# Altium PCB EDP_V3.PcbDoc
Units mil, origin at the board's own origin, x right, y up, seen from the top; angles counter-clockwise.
Board outline 1496.06 x 2204.77 mil, 2 copper layers (Top Layer, Bottom Layer); 19 components, 14 nets, 61 pads, 4 vias.
Unrouted connection lines stored in the file: 1.
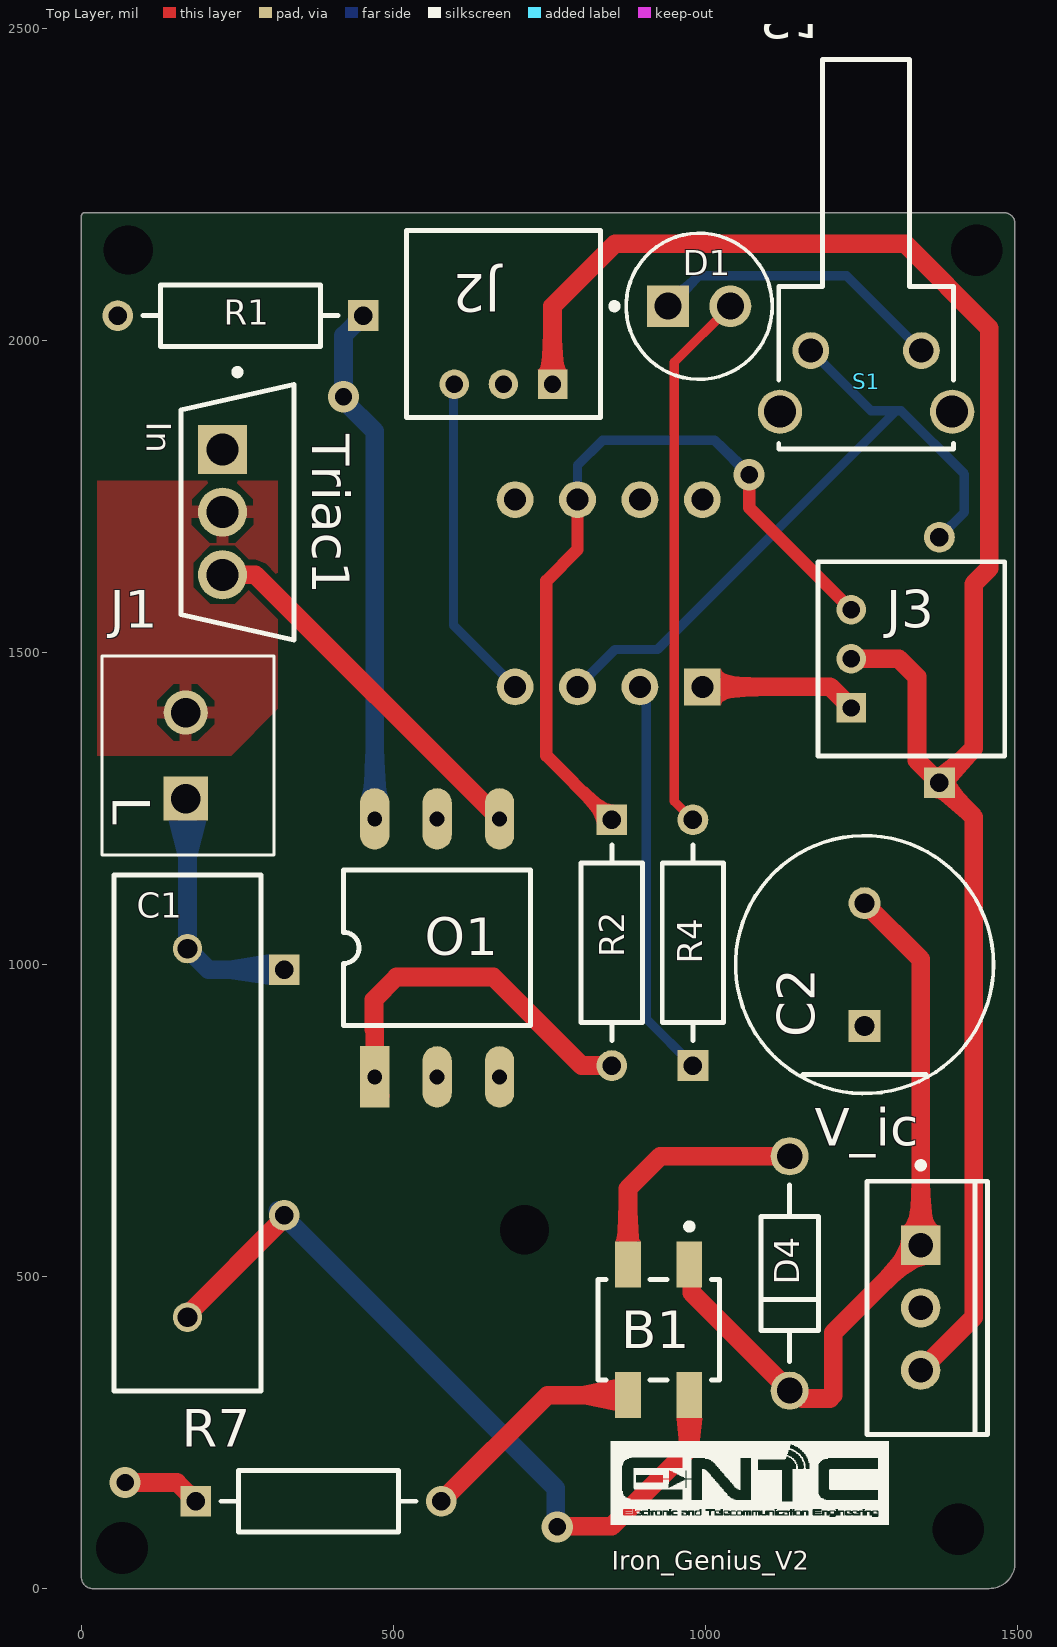
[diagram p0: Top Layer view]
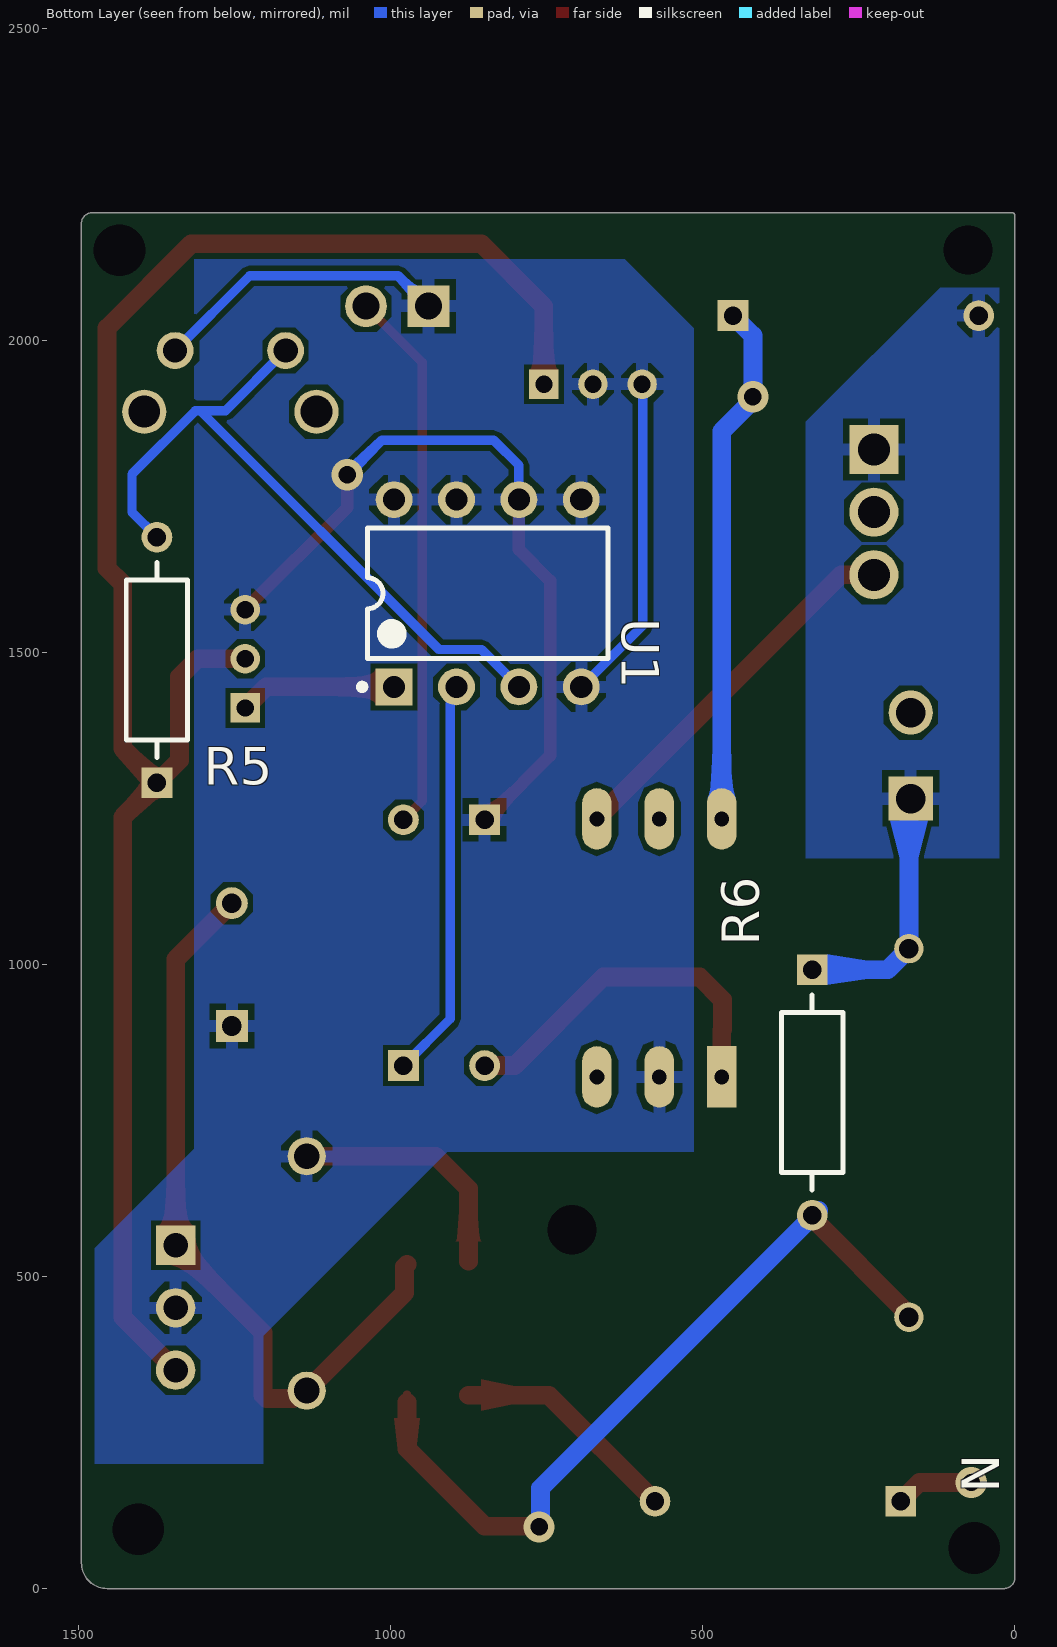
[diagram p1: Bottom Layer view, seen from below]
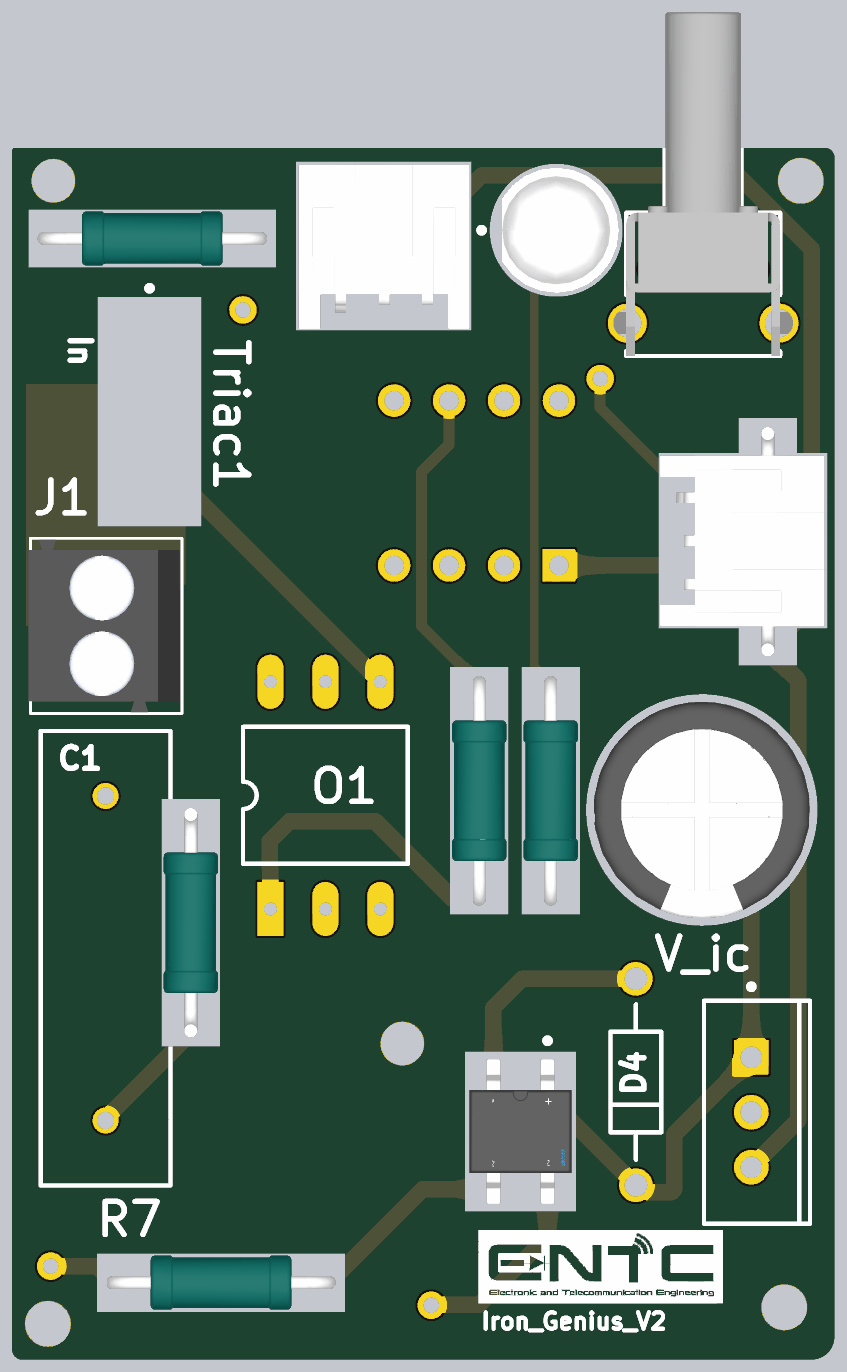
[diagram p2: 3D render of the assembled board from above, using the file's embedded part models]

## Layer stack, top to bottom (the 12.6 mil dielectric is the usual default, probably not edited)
Top Solder: solder mask 1, SM-001, Dk 4
Top Layer: signal copper 1.4
Dielectric 1: dielectric 12.6, FR-4, Dk 4.8
Bottom Layer: signal copper 1.4
Bottom Solder: solder mask 1, SM-001, Dk 4

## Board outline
0,18 0,2200 cw(c4.78,2200) 5.08,2204.77 cw(c5.23,2200.5) 5.9,2204.72 1479.28,2204.72 cw(c1479.28,2187.94) 1496.06,2187.94 1496.06,41.06 cw(c1455,41.06) 1455,0 18,0 cw(c18,18)

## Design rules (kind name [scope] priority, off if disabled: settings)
BoardOutlineClearance [All] p1: gap=11.81 ignorepadtopadclearanceinfootprint=FALSE except(15.75: Arc-SplitBarrior Arc-SplitContinuation Track-SplitBarrior Track-SplitContinuation SMDPad-SplitBarrior SMDPad-SplitContinuation THPad-SplitBarrior THPad-SplitContinuation Via-SplitBarrior Via-SplitContinuation Fill-SplitBarrior Fill-SplitContinuation Poly-SplitBarrior Poly-SplitContinuation Region-SplitBarrior Region-SplitContinuation Text-SplitBarrior Text-SplitContinuation)
Clearance "Clearance Different Nets" [All] p1: gap=7.87 ignorepadtopadclearanceinfootprint=FALSE except(3.5: Arc-Arc Arc-Track Arc-SMDPad Track-Track Track-SMDPad; 5: SMDPad-SMDPad SMDPad-Via THPad-Via Via-Via; 10: Arc-Via Arc-Text Track-Via Track-Text SMDPad-Text THPad-Text Via-Text Fill-Text Poly-Text Region-Text Text-Text; 19.68: THPad-THPad Via-Hole)
Clearance "Clearance Same Nets" [All] p2: gap=7.87 ignorepadtopadclearanceinfootprint=FALSE except(3.5: Arc-Arc Arc-Track Arc-SMDPad Track-Track Track-SMDPad SMDPad-SMDPad; 5: SMDPad-Via THPad-Via; 10: Arc-Via Arc-Text Track-Via Track-Text SMDPad-Text THPad-Text Via-Via Via-Text Fill-Text Poly-Text Region-Text Text-Text)
Clearance "Clearance Bottom Layer" [OnLayer('Bottom Layer')] p3: gap=8 ignorepadtopadclearanceinfootprint=TRUE except(10: Arc-Text Track-Text SMDPad-Text THPad-Text Via-Text Fill-Text Poly-Text Region-Text Text-Text)
Clearance "Clearance Top Layer" [OnLayer('Top Layer')] p4: gap=8 ignorepadtopadclearanceinfootprint=TRUE except(10: Arc-Text Track-Text SMDPad-Text THPad-Text Via-Text Fill-Text Poly-Text Region-Text Text-Text)
HoleSize [All] p1: absolutevalues=TRUE maxlimit=248.03 minlimit=7.87 maxpercent=80.000 minpercent=20.000
MinimumAnnularRing [All] p1: minimumring=5.12
MinimumSolderMaskSliver [All] p1: minsoldermaskwidth=3.94
PolygonConnect PolygonConnect_1 [All] p1: thpad.connectstyle=Relief thpad.reliefconductorwidth=20 thpad.reliefentries=4 thpad.polygonreliefangle="90 Angle" thpad.airgapwidth=10 smdpad.connectstyle=Relief smdpad.reliefconductorwidth=20 smdpad.reliefentries=4 smdpad.polygonreliefangle="90 Angle" smdpad.airgapwidth=10 via.connectstyle=Direct via.reliefconductorwidth=20 via.reliefentries=4 via.polygonreliefangle="90 Angle" via.airgapwidth=10
RoutingCorners [All] p1: cornerstyle=Round minsetback=100 maxsetback=100
RoutingVias [All] p1: holewidth=19.68 width=39.37 viastyle="Through Hole" minholewidth=7.87 minwidth=13.78 maxholewidth=39.37 maxwidth=78.74
SilkToSilkClearance [All] p1: silktosilkclearance=3.94
SilkToSolderMaskClearance [IsPad] p1: minsilkscreentomaskgap=3.94 clearancetoexposedcopper=TRUE
SolderMaskExpansion [All] p1: expansion=4 istentingtop=FALSE
SupplyNets "Schematic Supply Nets_1" [InNet('Triac output')] p1: voltage=0.000
Width [All] p1: maxlimit=100 minlimit=3.5 preferedwidth=15
25 further rules are at their usual default settings.

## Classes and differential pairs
component class EDP_IronGenius_V3: B1 C2 D1 D4 J1 J2 J3 O1 R1 R2 R4 R5 R6 R7 S1 Triac1 U1 V_ic

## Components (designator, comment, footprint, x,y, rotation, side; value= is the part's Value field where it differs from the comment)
B1 "Bridge_rectifier" "Bridge rectifier" 925,415 r270 top
C1 "" "Capacitor 470nF 400V AC" 170,435 r90 top value=470nF
C2 "Electrolytic cap" "Electrolytic cap" 1255,1000 r90 top value=220uF
D1 "LED_Ind" LED_ind 990,2055 r0 top
D4 "Zener diode" Diode 1130,495 r90 top
J1 "AC power_connector" "AC power_connector" 162.13,1340 r90 top
J2 "Jack_for_sensor" Sensor_jack 676.26,2026.46 r0 top
J3 "Slide switch connector" Sensor_jack 1330,1490 r270 top
O1 "MOC3021" DIP6 470,820 r90 top
R1 "10K resistor" "10K resistor" 255,2040 r180 top value=1kR
R2 "220ohm_res" 220ohm_res 850,1035 r270 top value=220R
R4 "220ohm_res" 220ohm_res 980,1035 r90 top value=220R
R5 "1M_ohm" 1M_om 1375,1488.15 r90 bottom value=1MR
R6 "1M_ohm" 1M_om 325,795 r270 bottom value=1MR
R7 "220ohm_res" 220ohm_res 380,140 r0 top value=220R
S1 "PushButton" PushButton 1257.42,1934.98 r270 top
Triac1 "Triac" "Triac BTA16-600" 235,1730 r0 top
U1 "PIC12F675-I/P" PDIP300-P8 845,1605 r90 bottom
V_ic "MC7805CTG" IC7805 1365,445 r0 top

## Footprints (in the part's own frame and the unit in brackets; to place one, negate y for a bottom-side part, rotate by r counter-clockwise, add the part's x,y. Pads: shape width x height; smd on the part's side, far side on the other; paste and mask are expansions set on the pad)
1M_om [mm]
  rect 1.25x1.25 hole 0.75 paste-2539.97 mask+0: 1(-5,0)
  round 1.25 hole 0.75 paste-2539.97 mask+0: 2(5,0)
  silkscreen extent -3.98,-1.25 3.98,1.25, body extent -5.3,-1.25 5.3,1.25, height 2.5
"10K resistor" [mm]
  rect 1.25x1.25 hole 0.75 paste-2539.97 mask+0: 1(-5,0)
  round 1.25 hole 0.75 paste-2539.97 mask+0: 2(5,0)
  silkscreen extent -3.98,-1.25 3.98,1.25, body extent -5.3,-1.25 5.3,1.25, height 2.5
220ohm_res [mm]
  rect 1.25x1.25 hole 0.75 paste-2539.97 mask+0: 1(-5,0)
  round 1.25 hole 0.75 paste-2539.97 mask+0: 2(5,0)
  silkscreen extent -3.98,-1.25 3.98,1.25, body extent -5.72,-1.35 5.72,1.35, height 0.25
"AC power_connector" [mm]
  rect 1.8x1.8 / inner round 1.8 / far side rect 1.8x1.8 hole 1.2: 1(-1.877,-0.127)
  round 1.8 hole 1.2: 2(1.623,-0.127)
  silkscreen extent -4.18,-3.73 3.92,3.27, body extent -4.13,-3.63 3.87,3.37, height 8.4
"Bridge rectifier" [mm]
  rect 1.875x1.05 smd paste+0 mask+0: 1(-2.658,1.25) 2(2.667,1.25) 3(-2.658,-1.25) 4(2.667,-1.25)
  silkscreen extent -4.32,-2.47 2.05,2.47, body extent -3.7,-2.58 3.7,2.58, height 0.25
"Capacitor 470nF 400V AC" [mm]
  round 1.2 hole 0.8: 1(0,0) 2(15,0)
  silkscreen extent -3,-3 18,3
Diode [mm]
  round 1.55 hole 1.05: 1(-4.516,-0.127) 2(5.024,-0.127)
  silkscreen extent -3.34,-1.3 3.85,1.05
DIP6 [mm]
  rect 2.5x1.2 hole 0.6: 1(0,0)
  oval 2.5x1.2 hole 0.6: 2(0,-2.54) 3(0,-5.08) 4(10.5,-5.08) 5(10.5,-2.54) 6(10.5,0)
  silkscreen extent 2.08,-6.35 8.41,1.27
"Electrolytic cap" [mm]
  rect 1.3x1.3 hole 0.8 paste-2539.97 mask+0: 1(-2.5,0)
  round 1.3 hole 0.8 paste-2539.97 mask+0: 2(2.5,0)
  silkscreen extent -5.25,-5.25 5.25,5.25, body extent -5.35,-5.35 5.35,5.35, height 0.25
IC7805 [mm]
  rect 1.6x1.6 hole 1: 1(-0.508,2.667)
  round 1.6 hole 1: 2(-0.508,0.127) 3(-0.508,-2.413)
  silkscreen extent -2.69,-5.02 2.21,6.05, body extent -2.67,-5.02 2.18,5.28, height 19.68
LED_ind [mm]
  rect 1.7x1.7 hole 1.1 paste-2539.97 mask+0: 1(-1.27,0)
  round 1.7 hole 1.1 paste-2539.97 mask+0: 2(1.27,0)
  silkscreen extent -3.57,-2.97 2.98,2.97, body extent -2.5,-2.9 2.89,2.9, height 9.11
PDIP300-P8 [mm] "8-Pin Plastic Dual In-Line Package (PDIP)"
  rect 1.5x1.5 hole 0.9: 1(-4.064,3.81)
  round 1.5 hole 0.9: 2(-4.064,1.27) 3(-4.064,-1.27) 4(-4.064,-3.81) 5(3.556,-3.81) 6(3.556,-1.27) 7(3.556,1.27) 8(3.556,3.81)
  silkscreen extent -4.19,-4.9 2.4,5.24, body extent -3.8,-4.9 3.3,4.9, height 4.32
PushButton [mm]
  round 1.5 hole 0.99: 1(-1.245,-2.25) 2(-1.245,2.25)
  round 1.8 hole 1.3: MH1(1.245,-3.505) MH2(1.245,3.505)
  silkscreen extent -13.09,-3.55 2.77,3.55, body extent -13.11,-4.2 2.76,4.2, height 7.01
Sensor_jack [mm]
  rect 1.2x1.2 hole 0.7 paste-2539.97 mask+0: 1(2,-2.45)
  round 1.2 hole 0.7 paste-2539.97 mask+0: 2(0,-2.45) 3(-2,-2.45)
  silkscreen extent -3.95,-3.8 3.95,3.8, body extent -4.04,-3.94 4.06,3.86, height 0.25
"Triac BTA16-600" [mm]
  rect 2x2 hole 1.3 paste-2539.97 mask+0: 1(-0.226,2.423)
  round 2 hole 1.3 paste-2539.97 mask+0: 2(-0.226,-0.127) 3(-0.226,-2.677)
  silkscreen extent -1.92,-5.33 2.68,5.7

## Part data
B1: "Bridge Rectifier Diode, 1 Phase, 0.8A, 1000V V(RRM), Silicon", Manufacturer=Diodes, Manufacturer Part Number=MB10F-13, Supplier Part Number=MB10F-13DICT-ND
C1: library part Component_2, "Film Capacitor, Polypropylene, 630V, 5% +Tol, 5% -Tol, 0.47uF, Through Hole Mount", Capacitor Type=FILM, Dielectric Material=Polypropylene, Manufacturer=KEMET, Manufacturer Part Number=R76PR3470SE30J, Max Operating Temperature=85°C, Min Operating Temperature=-55°C, Package Shape=Rectangular, Package Style=RadialMeter, Rated AC Voltage (URac)=400V, Rated DC Voltage (URdc)=630V, Supplier Part Number=399-7615-ND, Tolerance  (fill in as +-)=5%
C2: "Aluminum Electrolytic Capacitor, Polarized, Aluminum (wet), 50V, 20% +Tol, 20% -Tol, 220uF, Through Hole Mount", Capacitor Type=Aluminium, Leakage Current=110uA, Manufacturer=Panasonic, Manufacturer Part Number=EEU-FR1H221B, Manufacturer Series=FR, Max Operating Temperature=105°C, Min Operating Temperature=-40°C, Package Shape=Cylindrical, Package Style=RadialMeter, Rated DC Voltage (URdc)=50V, Ripple Current=1.155A, Supplier Part Number=P15375CT-ND, Tolerance  (fill in as +-)=20%
D1: "Single Color LED, Yellow, Tinted Diffused, T-1, 3mm", Color=Yellow, Forward Current=7mA, Forward Voltage=2.7V, Manufacturer="Broadcom Avago", Manufacturer Part Number=HLMP-1719, Max Operating Temperature=100°C, Min Operating Temperature=-40°C, Supplier Part Number=516-1309-ND
D4: library part Diode, "Rectifier Diode, 1 Phase, 1 Element, 1A, 1000V V(RRM), Silicon, DO-41", Case Connection=Isolated, Forward Voltage=1.1V, Manufacturer="ON Semiconductor", Manufacturer Part Number=1N4007RLG, Max Operating Temperature=175°C, Max Output current=1A, Min Operating Temperature=-65°C, Non-rep Pk Forward Current-Max=30A, Package Body Material=Plastic, Package Shape=Round, Package Style="LONG FORMMeter", Peak Reflow Temperature (Cel)=260°C, Rep Pk Reverse Voltage-Max=1kV, Supplier Part Number=1N4007RLGOSCT-ND, Time @ Peak Reflow Temperature-Max (s)=40s
J1: "Barrier Strip Terminal Block, 10A, 1 Row(s), 1 Deck(s)", Current Rating=10A, Manufacturer="On-Shore Technology", Manufacturer Part Number=OSTTE020104, Voltage Rating=125V
J2: "Conn Shrouded Header (4 Sides) HDR 3 POS 2mm Solder RA Side Entry Thru-Hole Box", Manufacturer=JST, Manufacturer Part Number=S3B-PH-K-S(LF)(SN), Supplier Part Number=306-S3BPHKSLFSN
J3: library part Jack_for_sensor, "Conn Shrouded Header (4 Sides) HDR 3 POS 2mm Solder RA Side Entry Thru-Hole Box", Manufacturer=JST, Manufacturer Part Number=S3B-PH-K-S(LF)(SN), Supplier Part Number=306-S3BPHKSLFSN
O1: "OPTOISOLATOR 4.17KV TRIAC 6DIP", Manufacturer="ON Semiconductor / Fairchild", Manufacturer Part Number=MOC3021M, Supplier Part Number=MOC3021MFS-ND
R1: "Fixed Resistor, Thin Film, 0.6W, 1000ohm, 350V, 1% +/-Tol, 50ppm/Cel, Through Hole Mount", Manufacturer=Vishay, Manufacturer Part Number=MRS25000C1001FCT00, Max Operating Temperature=155°C, Min Operating Temperature=-55°C, Package Length=6.5mm, Package Style=AXIAL, Power=600mW, Rated Temperature=70°C, Resistor Type="FIXED RESISTOR", Temperature Coefficient (ppm/Cel)=50, Tolerance=1%, Working Voltage=350V
R2 R4 R7: "Fixed Resistor, Metal Film, 0.25W, 220ohm, 200V, 1% +/-Tol, 50ppm/Cel, Through Hole Mount", Manufacturer="Vishay Beyschlag", Manufacturer Part Number=MBA02040C2200FC100, Max Operating Temperature=155°C, Min Operating Temperature=-55°C, Package Length=3.6mm, Package Shape=Tubular, Package Style=AXIAL, Power=400mW, Rated Temperature=70°C, Resistor Type="FIXED RESISTOR", Temperature Coefficient (ppm/Cel)=50, Tolerance=1%, Working Voltage=200V
R5 R6: "Fixed Resistor, Metal Film, 0.5W, 1000000ohm, 3500V, 1% +/-Tol, 200ppm/Cel, Through Hole Mount", Manufacturer="Vishay BCcomponents", Manufacturer Part Number=HVR3700001004FR500, Max Operating Temperature=155°C, Min Operating Temperature=-55°C, Package Length=12mm, Package Shape=Tubular, Package Style=AXIAL, Power=500mW, Rated Temperature=70°C, Resistor Type="FIXED RESISTOR", Temperature Coefficient (ppm/Cel)=200, Tolerance=1%, Working Voltage=3.5kV
S1: "Keypad Switch, 1 Switches, SPST, Momentary, 0.05A, 24VDC, 2.06N, 4 PCB Hole Cnt, Solder Terminal, Through Hole-straight", Actuator Color=Black, Contact Current(DC)-Max=50mA, Contact DC Max Rating R Load=.05A@24VDC, Contact Resistance=0.1mR, Contact Voltage(DC)-Max=24V, Dielectric Withstand Volts=500VACV, Insulation Resistance=100MR, Manufacturer="TE Connectivity", Manufacturer Part Number=2-1825910-7, Max Operating Temperature=85°C, Min Operating Temperature=-35°C, Operating Force-Max=2.06N, Supplier Part Number=450-1642-ND
Triac1: "Snubberless TRIAC, 600V V(DRM), 16A I(T)RMS, TO-220AB", Case Connection=Isolated, Hold Current=35mA, Leakage Current-Max=2mA, Manufacturer=STMicroelectronics, Manufacturer Part Number=BTA16-600CWRG, Max Operating Temperature=125°C, Min Operating Temperature=-40°C, Package Body Material=Plastic, Package Shape=Rectangular, Package Style="FLANGE MOUNTMeter", Repetitive Peak Off-state Voltage=600V, RMS Current (Irms)=16A, Supplier Part Number=511-BTA16-600CW
U1: library part CMP-0190-00021-1, "RISC Microcontroller, 8-Bit, FLASH, PIC CPU, 20MHz, CMOS, PDIP8", Case/Package=DIP, Clock Frequency=20MHz, Manufacturer=Microchip, Max Operating Temperature=85°C, Max Supply Current=15mA, Max Supply Voltage=5.5V, Min Operating Temperature=-40°C, Min Supply Voltage=4.5V, Nominal Supply Voltage=5V, Package Body Material=Plastic, Package Equivalence Code=DIP8,.3, Package Shape=Rectangular, Power Supplies=2.5, Temperature Grade=INDUSTRIAL
V_ic: "Fixed Positive Standard Regulator, 5VBIPolar", Dropout Voltage1-Nom=2V, Input Voltage Absolute-Max=35V, Manufacturer="ON Semiconductor", Max Supply Voltage=20V, Min Input Voltage=7.5V, Operating Temperature, TJ-Max=125°C, Operating Temperature, TJ-Min=0°C, Output Current1-Max=1A, Output Voltage1-Max=5.25V, Output Voltage1-Min=4.75V, Output Voltage1-Nom=5V, Package Equivalence Code=SIP3,.1TB, Package Shape=Rectangular, Peak Reflow Temperature (Cel)=260°C, Time @ Peak Reflow Temperature-Max (s)=40s, Voltage Tolerance-Max=5%

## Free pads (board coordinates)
  round 60 hole 82.68: 2(1405,95) 3(1435,2145) 5(65,65)
  round 60 hole 78.74: 4(75,2145) 6(710,575)

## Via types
v1: diameter 50, hole 28, Top Layer to Bottom Layer, 4 vias

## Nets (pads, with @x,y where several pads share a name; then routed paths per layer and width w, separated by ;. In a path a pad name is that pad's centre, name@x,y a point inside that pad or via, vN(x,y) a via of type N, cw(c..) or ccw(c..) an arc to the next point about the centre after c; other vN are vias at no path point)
+Vcc: J2.1 J3.2 R5.1 V_ic.3 | length 2972.5
  Top Layer w15: J2.1@753.74,1943.54 J2.1@755,1944.8
  Top Layer w30: J2.1@755,1944.8 755,2055 855,2155 1320,2155 1455,2020 1455,1635 1430,1610 1430,1346.3 R5.1 ; J3.2 1310,1490 1338.95,1461.05 1338.95,1327.35 R5.1 ; V_ic.3 1430,435 1430,1236.3 R5.1
Live: C1.2 J1.1 R1.2 R6.1 Triac1.1 | length 411.6
  Bottom Layer w15: J1.1@170,1261.1 J1.1@175,1266.1
  Bottom Layer w30: J1.1@170,1261.1 C1.2 203.7,991.85 R6.1
NetB1_1: B1.1 C2.2 D4.1 V_ic.1 | length 1230.2
  Top Layer w15: 1199.58,304.58 1205,310
  Top Layer w30: B1.1 978.16,515.7 978.16,474.05 D4.1 1143.39,317.2 1156.02,304.58 1199.58,304.58 ; 1205,310 1205,410 V_ic.1 1345,1008.43 C2.2
NetB1_2: B1.2 C1.1 R6.2 | length 1264
  Top Layer w15: C1.1 C1.1@170,439.07 ; R6.2@325,594.07 R6.2 ; B1.2@974.21,298.76 B1.2
  Top Layer w30: C1.1@170,439.07 R6.2@325,594.07 ; v1(762.62,98.89) 763.73,100 850,100 974.21,224.21 B1.2@974.21,298.76
  Bottom Layer w30: R6.2@315,606 317.15,606 R6.2 ; R6.2@328,593 760.35,160.65 760.35,101.15 v1(762.62,98.89)
NetB1_4: B1.4 R7.2 | length 369.4
  Top Layer w30: R7.2 746.85,310 805,310 B1.4
NetD1_2: D1.2 R4.2 | length 872.8
  Top Layer w15: R4.2 950.1,1261.75 950.1,1965.1 D1.2
NetJ1_2: J1.2 Triac1.2
NetJ3_1: J3.1 U1.1 | length 252.5
  Top Layer w30: U1.1 1199.8,1445 J3.1
NetO1_1: O1.1 R2.2 | length 598.5
  Top Layer w15: 468.83,896.17 470,895
  Top Layer w20: O1.1@470,803.38 O1.1@483.62,789.76
  Top Layer w30: 468.83,896.17 468.83,943.83 505,980 660,980 801.85,838.15 R2.2 ; O1.1 470,895
NetO1_4: O1.4 Triac1.3 | length 606
  Top Layer w30: Triac1.3 278.78,1624.61 O1.4
NetO1_6: O1.6 R1.1 | length 839.4
  Bottom Layer w30: v1(420,1910) 420,1904.59 470,1854.59 O1.6@470,1229.66 ; v1@420,1914.81 420,2008.15 R1.1
NetR4_1: R4.1 R5.2 S1.1 U1.2 U1.3 | length 1789.5
  Bottom Layer w15: U1.3 855,1505 923.15,1505 1305.74,1887.59 1313.41,1887.59 ; U1.2 903.43,1436.57 903.43,1419.12 905,1417.55 905,913.15 R4.1 ; S1.1 1265.24,1887.59 1313.41,1887.59 ; R5.2 1415,1725 1415,1786 1313.41,1887.59
Neutral: R7.1 | length 125.6
  Top Layer w30: v1(70,170) 153.15,170 R7.1
"Triac output": B1.3 C2.1 D1.1 D4.2 J2.2 J2.3 J3.3 O1.2 R2.1 S1.2 U1.4 U1.5 U1.6 U1.7 U1.8 V_ic.2 | length 2671.4
  Top Layer w20: U1.6 795,1665 745,1615 745,1335 833.54,1246.46 835.39,1246.46 848.15,1233.7 R2.1@848.15,1231.85 ; v1(1070,1785) 1070,1732.28 J3.3
  Top Layer w30: B1.3@875.79,524.65 875.79,640.79 927.8,692.8 D4.2
  Bottom Layer w10: U1.4@686.64,1453.36 686.64,1461.64 697.97,1461.64 U1.4@703.99,1467.66
  Bottom Layer w15: J2.3@596.26,1943.54 596.26,1543.74 686.64,1453.36 U1.4 ; U1.6 795,1800 835,1840 1015,1840 v1(1070,1785) ; D1.1 988.84,2103.84 1226.16,2103.84 S1.2
pads on no net: O1.3 O1.5 S1.MH1 S1.MH2

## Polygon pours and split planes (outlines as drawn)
"Triac output" on Bottom Layer "TRIAC_OUTPUT_L02_P003" (solid, remove dead copper, pour order 3): 625,2130 1315,2130 1315,705 1475,545 1475,200 1205,200 1205,405 910,700 515,700 515,2020
Live on Bottom Layer "LIVE_L02_P000" (solid, pour order 0): 25,2085 120,2085 335,1870 335,1170 25,1170
NetJ1_2 on Top Layer "NETJ1_2_L01_P001" (solid, pour order 1): 25,1775 315,1775 315,1410 240,1335 25,1335

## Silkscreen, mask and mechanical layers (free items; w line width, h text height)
Top Overlay:
  region: 1270.68,120.57 1269.6,120.57 1269.6,122.75 1273.95,122.75 1273.95,121.66 1275.04,121.66 1275.04,120.57 1271.77,120.57
  region: 1239.13,122.75 1241.31,122.75 1241.31,121.66 1236.96,121.66 1236.96,122.75 1238.04,122.75
  region: 1228.25,122.75 1230.43,122.75 1230.43,121.66 1227.16,121.66 1227.16,122.75
  region: 1203.23,120.57 1201.05,120.57 1201.05,122.75 1205.4,122.75 1205.4,120.57 1204.32,120.57
  region: 1151,122.75 1151,119.49 1146.65,119.49 1146.65,122.75 1149.91,122.75
  region: 1130.33,120.57 1131.42,120.57 1131.42,119.49 1127.07,119.49 1127.07,120.57 1129.24,120.57
  region: 1055.26,122.75 1056.34,122.75 1056.34,119.49 1051.99,119.49 1051.99,122.75 1054.17,122.75
  region: 1045.46,122.75 1048.73,122.75 1048.73,119.49 1042.2,119.49 1042.2,122.75 1044.38,122.75
  region: 1031.32,121.66 1031.32,122.75 1035.67,122.75 1035.67,121.66 1032.41,121.66
  region: 1021.53,122.75 1021.53,121.66 1017.18,121.66 1017.18,122.75 1020.44,122.75
  region: 889.88,122.75 894.23,122.75 894.23,121.66 889.88,121.66
  region: 926.87,120.57 926.87,119.49 922.52,119.49 922.52,122.75 926.87,122.75 926.87,121.66
  region: 967.13,119.49 964.95,119.49 964.95,120.57 968.22,120.57 968.22,119.49
  region: 986.71,121.66 986.71,122.75 991.06,122.75 991.06,119.49 985.62,119.49 985.62,121.66
  region: 5 vertices and 31 holes, not listed, extent 848.53,102.08 1293.53,235.9
  text "In" at 105,1870 h39.37 r270
  text "L" at 50,1270 h60 r270
  text "Iron_Genius_V2" at 850,30 h30
Bottom Overlay:
  text "N" at 85,215 h60 r90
